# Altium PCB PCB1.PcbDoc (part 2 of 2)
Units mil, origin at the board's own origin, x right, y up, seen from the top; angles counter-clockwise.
Board outline 1707.5 x 1259.84 mil, 4 copper layers (Top Layer, GND, Sign, Bottom Layer), stack 23.756 mil thick; 63 components, 56 nets, 288 pads, 252 vias.
Unrouted connection lines stored in the file: 1.
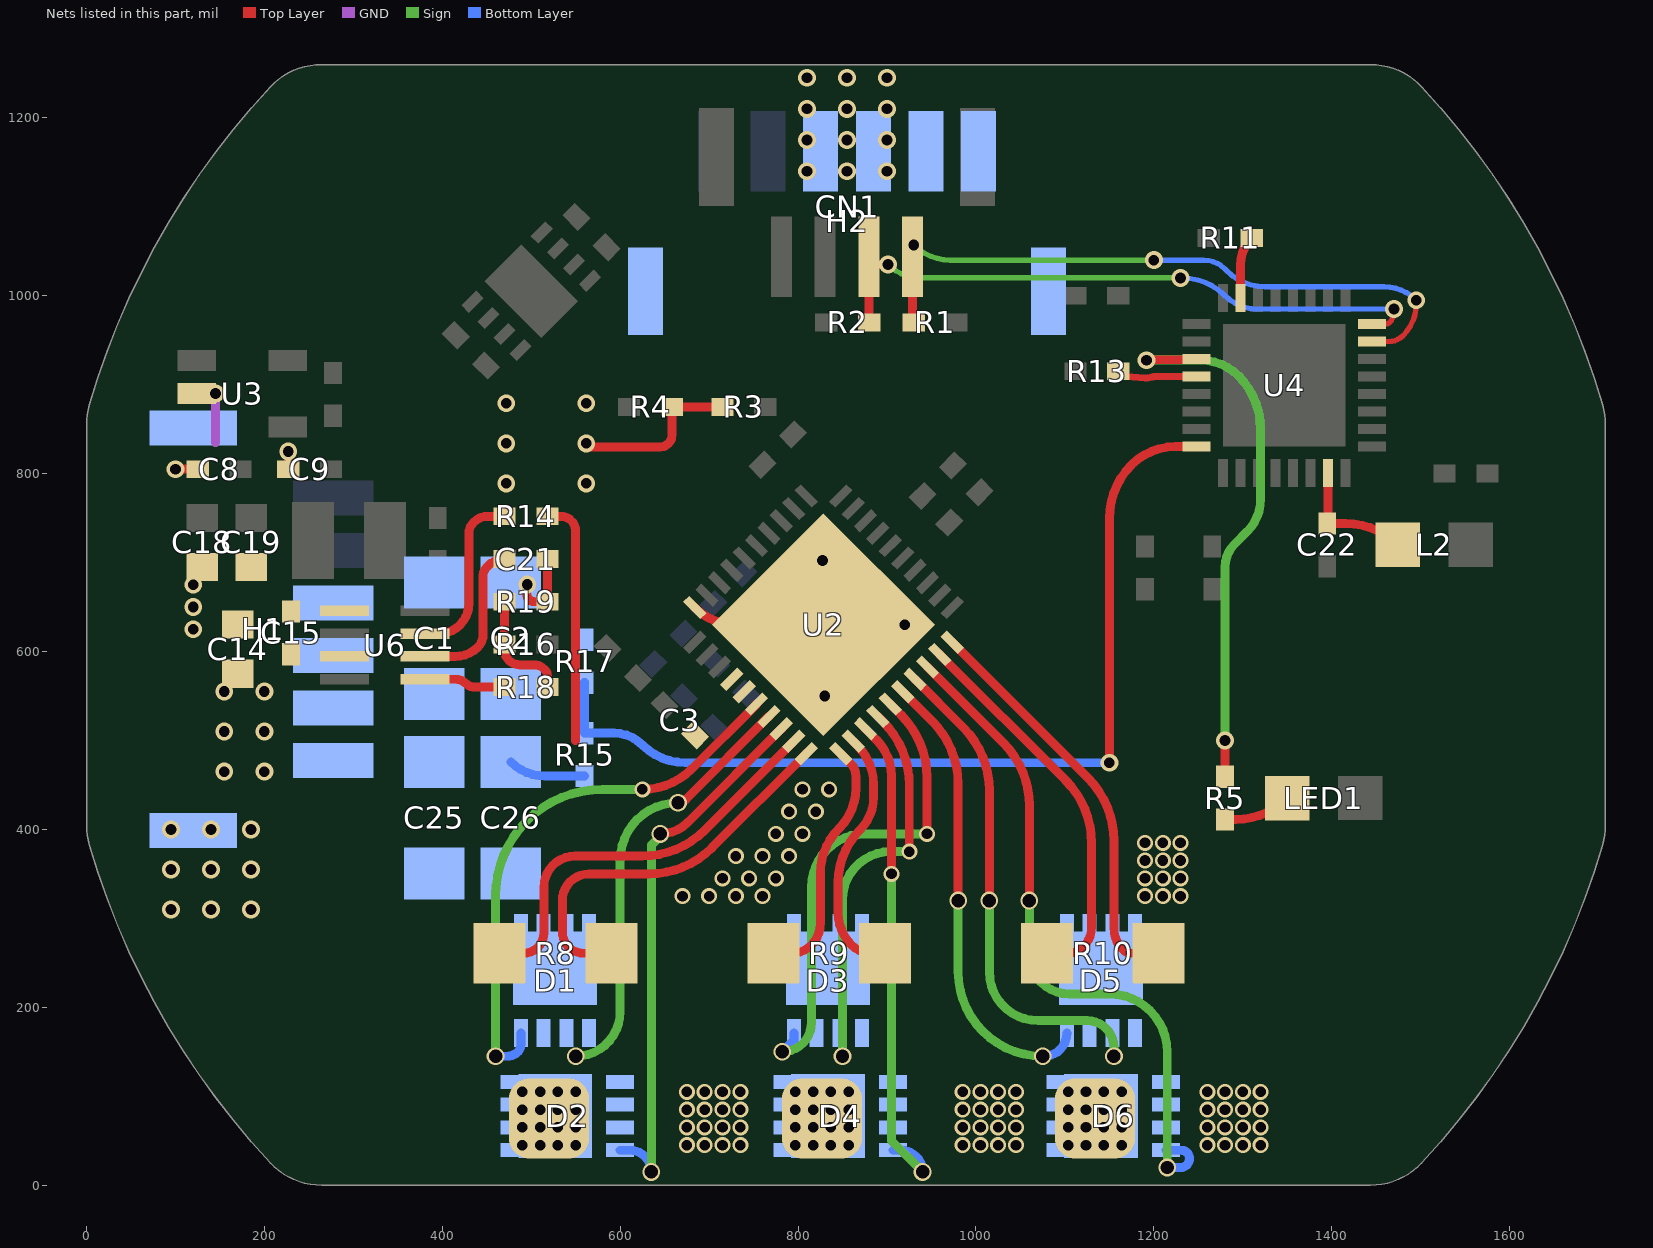
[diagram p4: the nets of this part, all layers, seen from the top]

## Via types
v1: diameter 18, hole 12, Top Layer to Bottom Layer, tented both sides, 138 vias
v2: diameter 20, hole 12, Top Layer to Bottom Layer, tented both sides, 100 vias
v3: diameter 20, hole 15, Top Layer to Bottom Layer, tented both sides, 14 vias

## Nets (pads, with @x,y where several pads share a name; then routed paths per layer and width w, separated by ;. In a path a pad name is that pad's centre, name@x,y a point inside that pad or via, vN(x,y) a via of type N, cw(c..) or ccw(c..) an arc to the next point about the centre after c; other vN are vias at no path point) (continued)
NetC21_2: C21.2 U6.2 | length 177.5
  Top Layer w10: U6.2@380.55,594.41 414.43,594.41 ccw(c414.43,630.57) 440,605 ccw(c425.51,619.49) 446,619.49 446,685.88 cw(c456,685.84) 446.87,689.91 cw(c466.24,681.2) 451.22,696.22 cw(c470,677.44) C21.2@470,704
NetC22_2: C22.2 L2.2 U4.15 | length 142.4
  Top Layer w10: U4.15@1395.78,800.79 1395.78,745.88 cw(c1393.12,745.88) C22.2@1395,744 1415.48,744 cw(c1415.48,661.38) L2.2@1473.9,719.8
NetD1_G: D1.G U2.6 | length 898.7
  Top Layer w10: U2.6@753.34,540.92 680.34,467.92 ; 680.34,467.92 cw(c625,523.27) v1(625,445) ccw(c625,523.27) 680.34,467.92
  Sign w10: v3(460,145) 460,325 ; 580,445 v1(625,445) ; 460,325 cw(c580,325) 580,445 ccw(c580,325) 460,325
  Bottom Layer w10: v3(460,145) 472.93,145 ; D1.G@488.34,170.94 D1.G@488.34,158.07 ; 472.93,145 ccw(c472.93,162.07) 485,150 cw(c472.93,162.07) 472.93,145 ; D1.G@488.34,158.07 cw(c476.93,158.07) 485,150 ccw(c476.93,158.07) D1.G@488.34,158.07
NetD2_G: D2.G U2.8 | length 650.9
  Top Layer w10: U2.8@781.18,513.08 675.89,407.8 ; 675.89,407.8 cw(c645,438.69) v3(645,395) ccw(c645,438.69) 675.89,407.8
  Sign w10: v3(635,15) 635,382.29 645,392.29 v3(645,395)
  Bottom Layer w10: D2.G@599.61,39.33 610.67,39.33 cw(c610.67,15) v3(635,15)
NetD2_S: D2.S R8.2 U2.9 | length 633.5
  Top Layer w10: R8.2@464.6,260.79 R8.2@491.3,260.79 ; U2.9@795.1,499.16 695.23,399.29 ; R8.2@491.31,260.79 ccw(c491.31,283.69) 514.21,283.69 ; R8.2@491.31,260.79 ccw(c491.31,283.69) 514.21,283.69 ; 514.21,283.69 514.21,335.07 ; 514.21,335.07 cw(c549.14,335.07) 549.14,370 ; 514.21,335.07 cw(c549.14,335.07) 549.14,370 ; 549.14,370 624.52,370 ; 624.52,370 ccw(c624.52,470) 695.23,399.29 ; 624.52,370 ccw(c624.52,470) 695.23,399.29
  other v1: 675,45 695,45 715,45 735,45 675,65 695,65 715,65 735,65 675,85 695,85 715,85 735,85 675,105 695,105 715,105 735,105
NetD3_G: D3.G U2.15 | length 631.6
  Top Layer w10: U2.15@903.67,540.92 915.71,528.88 ; v1(945,395) 945,458.17 ; 915.71,528.88 cw(c845,458.17) 945,458.17 ccw(c845,458.17) 915.71,528.88
  Sign w10: v3(782.17,150) ccw(c782.17,182.83) 815,182.83 815,335 cw(c875,335) 875,395 v1(945,395)
  Bottom Layer w10: v3(782.17,150) 795.24,163.07 D3.G@795.24,170.94
NetD4_G: D4.G U2.13 | length 614.9
  Top Layer w10: U2.13@875.83,513.08 888.09,500.82 ; v1(905,350) 905,460 ; 888.09,500.82 cw(c847.28,460) 905,460 ccw(c847.28,460) 888.09,500.82
  Sign w10: v1(905,350) 905,50 v3(940,15)
  Bottom Layer w10: D4.G@906.5,39.33 915.67,39.33 cw(c915.67,15) v3(940,15)
NetD4_S: D4.S R9.2 U2.12 | length 405
  Top Layer w10: 845,339.64 cw(c930.36,339.64) 870,400 ; 845,306.21 845,339.64 ; U2.12@861.91,499.16 U2.12@866.57,494.49 ; 870,400 ccw(c833.79,436.21) 885,436.21 ; 885,436.21 885,450 ; R9.2@897.5,260.79 R9.2@882.23,260.79 ; 860,270 ccw(c882.23,292.23) R9.2@882.23,260.79 ; 860,270 cw(c896.21,306.21) 845,306.21 ccw(c896.21,306.21) 860,270 ; 860,270 ccw(c882.23,292.23) R9.2@882.23,260.79 ; U2.12@866.57,494.49 cw(c822.08,450) 885,450 ccw(c822.08,450) U2.12@866.57,494.49
  other v1: 985,45 1005,45 1025,45 1045,45 985,65 1005,65 1025,65 1045,65 985,85 1005,85 1025,85 1045,85 985,105 1005,105 1025,105 1045,105
NetD5_G: D5.G U2.16 | length 606.1
  Top Layer w10: U2.16@917.59,554.83 950.71,521.71 ; v3(980,320) 980,451 ; 950.71,521.71 cw(c880,451) 980,451 ccw(c880,451) 950.71,521.71
  Sign w10: 980,240 ccw(c1075,240) v3(1075,145) ; 980,240 v3(980,320)
  Bottom Layer w10: v3(1075,145) 1076.19,145 ccw(c1076.18,170.94) D5.G@1102.12,170.94
NetD6_G: D6.G U2.18 | length 1043.1
  Top Layer w10: U2.18@945.43,582.67 1030.71,497.39 ; v3(1060,320) 1060,426.68 ; 1030.71,497.39 cw(c960,426.68) 1060,426.68 ccw(c960,426.68) 1030.71,497.39
  Sign w10: 1060,259.87 v3(1060,320) ; 1150,215 1104.87,215 ; v3(1215,20) 1215,150 ; 1104.87,215 cw(c1104.87,259.87) 1060,259.87 ccw(c1104.87,259.87) 1104.87,215 ; 1150,215 cw(c1150,150) 1215,150 ccw(c1150,150) 1150,215
  Bottom Layer w10: D6.G@1213.39,39.33 1230.67,39.33 cw(c1230.67,30) 1240,30 ; v3(1215,20) 1230,20 ; 1240,30 cw(c1230,30) 1230,20 ccw(c1230,30) 1240,30
NetD6_S: D6.S R10.2 U2.19 | length 562.3
  Top Layer w10: U2.19@959.35,596.59 1100.71,455.23 ; R10.2@1079.6,260.79 R10.2@1103.83,260.81 ; 1130,290 1130,384.52 ; 1100.71,455.23 cw(c1030,384.52) 1130,384.52 ccw(c1030,384.52) 1100.71,455.23 ; R10.2@1103.83,260.81 ccw(c1102.77,286.62) 1121.04,268.36 ; R10.2@1103.84,260.81 ccw(c1102.77,286.62) 1121.04,268.36 ; 1121.04,268.36 ccw(c1099.39,290) 1130,290 cw(c1099.39,290) 1121.04,268.36
  other v1: 1260,45 1280,45 1300,45 1320,45 1260,65 1280,65 1300,65 1320,65 1260,85 1280,85 1300,85 1320,85 1260,105 1280,105 1300,105 1320,105
NetLED1_1: LED1.1 R5.2 | length 76.2
  Top Layer w10: R5.2@1280,411.12 1291.81,411.12 ccw(c1291.81,493.07) LED1.1@1349.75,435.12
NetR11_2: R11.2 U4.31 | length 70.7
  Top Layer w10: U4.31@1297.36,997.64 1297.36,1034.48 cw(c1340.52,1034.48) R11.2@1310,1065
NetR13_2: R13.2 U4.4 | length 90.3
  Top Layer w8: R13.2@1160,915 1168.5,909 1190.29,907.57 ccw(c1191.65,927.53) 1198.19,908.63 cw(c1200.79,901.06) 1200.79,909.06 U4.4@1248.15,909.06
NetR14_2: R14.2 U6.3 | length 198.1
  Top Layer w10: U6.3@380.55,620 395.86,620 ccw(c395.86,654.14) 420,630 ccw(c395.86,654.14) 430,654.14 430,732.88 ; 430,732.93 cw(c447.07,732.93) 435,745 435.86,745.86 cw(c450.69,731.03) 450.69,752 R14.2@470,752
NetR15_1: R15.1 R17.1 U4.8 | length 1075.9
  Top Layer w10: v2(1150,475) 1150,749.64 cw(c1235.36,749.64) 1175,810 cw(c1224.06,760.94) 1224.06,830.32 U4.8@1248.15,830.32
  Bottom Layer w10: R17.1@560,565 R15.1@560,508.2 592.97,508.2 593.03,508.2 cw(c593.13,463.13) 625,495 ; 625,495 ccw(c673.28,543.28) 673.32,475 ; 673.36,475 v2(1150,475)
NetR16_1: R16.1 R18.2 R19.2 | length 130.9
  Top Layer w10: R19.2@470,656 R16.1@470,608 470,602.07 ccw(c487.07,602.07) 475,590 ccw(c487.07,602.07) 487.07,585 502.93,585 cw(c502.93,567.93) 515,580 ; 515,580 cw(c507.27,572.27) 518.2,572.27 R18.2@518.2,560
NetR18_1: R18.1 U6.1 | length 91.8
  Top Layer w10: U6.1@380.55,568.82 415.78,568.82 cw(c415.78,555.78) 425,565 ; 425,565 ccw(c437.07,577.07) 437.07,560 R18.1@470,560
PGND: C1.1 C2.1 C8.1 C9.1 C14.1 C15.1 C18.1 C19.1 C21.1 C25.1 C26.1 H1.3 H1.4 H1.7 H1.8 H2.3 H2.4 H2.7 H2.8 R3.2 R4.2 R8.1 R9.1 R10.1 R17.2 R19.1 U2.10 U2.11 U2.20 U2.40 U2.41 U3.2 U6.5 | length 2089.3
  Top Layer w10: v2(100,805) C8.1@125,805 ; U3.2@123.81,890 v2(145,890) ; C9.1@226.8,805 v2(226.8,824.79) ; v2(495.48,675.35) 495,675.35 495,665 ccw(c504,665) 504,656 R19.1@518.2,656 C21.1@518.2,704 ; 535,285 ccw(c559.21,285) 559.21,260.79 R8.1@590,260.79 ; 535,285 535,320 ; v2(561.82,834) ccw(c565.82,834) 565.82,830 645,830 ccw(c645,843.2) 658.2,843.2 R4.2@658.2,875 R3.2@715,875 ; 565,350 632.35,350 ; R9.1@772.1,260.79 792.77,260.79 ccw(c792.77,292.23) 815,270 ; U2.10@809.01,485.24 703.07,379.29 ; 825,350 cw(c897.43,350) 846.2,401.2 ; 825,294.14 825,350 ; U2.41@828.5,630 U2.41@730.8,630 ; U2.11@847.99,485.24 859.18,474.05 ; 865,446.57 865,460 ; U2.20@973.27,610.51 1125.71,458.06 ; 1155,289.14 ccw(c1189.14,289.14) 1165,265 ; 1155,289.14 1155,387.35 ; 1165,265 ccw(c1175.16,275.16) 1175.16,260.79 R10.1@1205,260.79 ; 632.35,350 ccw(c632.35,450) 703.06,379.29 ; 632.35,350 ccw(c632.35,450) 703.06,379.29 ; U2.41@730.79,630 cw(c730.79,696.54) U2.40@683.74,649.49 ccw(c730.79,696.54) 687.88,645.69 ccw(c730.79,696.54) U2.41@730.79,630 ; 846.2,401.2 ccw(c800.86,446.57) 865,446.57 cw(c800.86,446.57) 846.2,401.2 ; 859.18,474.05 cw(c845.12,460) 865,460 ccw(c845.12,460) 859.18,474.05 ; 1125.71,458.06 cw(c1055,387.35) 1155,387.35 ccw(c1055,387.35) 1125.71,458.06 ; 535,320 cw(c565,320) 565,350 ccw(c565,320) 535,320 ; 815,270 ccw(c790.86,294.14) 825,294.14 cw(c790.86,294.14) 815,270
  GND w10: 145,835 v2(145,890)
  other v1: 670,325 700,325 730,325 760,325 1190,325 1210,325 1230,325 715,345 745,345 775,345 1190,345 1210,345 1230,345 1190,365 1210,365 1230,365 730,370 760,370 790,370 1190,385 1210,385 1230,385 775,395 805,395 790,420 820,420 805,445 835,445
  other v2: 95,310 140,310 185,310 95,355 140,355 185,355 95,400 140,400 185,400 830,550 120,625 920,630 120,650 120,675 827.42,702.42 471.82,789 561.82,789 471.82,834 471.82,879 561.82,879 810,1140 855,1140 900,1140 810,1175 855,1175 900,1175 810,1210 855,1210 900,1210 810,1245 855,1245 900,1245
SHA: D1.S D2.D pad.2@520,75 U2.7 | length 492.5
  Top Layer w10: v3(665,430) ccw(c665,442.71) 673.99,433.72 U2.7@767.26,526.99
  Sign w10: v3(550,145) ccw(c550,195) 600,195 ; 600,365 cw(c665,365) v3(665,430) ; 600,195 600,365
  other v1: 490,45 510,45 530,45 550,45 490,65 510,65 530,65 550,65 490,85 510,85 530,85 550,85 490,105 510,105 530,105 550,105
SHB: D3.S D4.D pad.2@826.89,75 U2.14 | length 607.3
  Top Layer w10: U2.14@889.75,526.99 U2.14@895.71,521.03 ; v1(925,375) 925,450.32 ; U2.14@895.71,521.03 cw(c825,450.32) 925,450.32 ccw(c825,450.32) U2.14@895.71,521.03
  Sign w10: v3(850,145) 850,321.2 ; v1(925,375) 903.8,375 ; 903.8,375 ccw(c903.8,321.2) 850,321.2 cw(c903.8,321.2) 903.8,375
  other v1: 796.89,45 816.89,45 836.89,45 856.89,45 796.89,65 816.89,65 836.89,65 856.89,65 796.89,85 816.89,85 836.89,85 856.89,85 796.89,105 816.89,105 836.89,105 856.89,105
SHC: D5.S D6.D pad.2@1133.78,75 U2.17 | length 769.6
  Top Layer w10: U2.17@931.51,568.76 985.71,514.56 ; v3(1015,320) 1015,443.84 ; 985.71,514.55 cw(c915,443.84) 1015,443.84 ccw(c915,443.84) 985.71,514.55
  Sign w10: 1015,239.99 v3(1015,320) ; 1125,185 1069.99,185 ; v3(1155,145) 1155,155 ; 1069.99,185 cw(c1069.99,239.99) 1015,239.99 ccw(c1069.99,239.99) 1069.99,185 ; 1125,185 cw(c1125,155) 1155,155 ccw(c1125,155) 1125,185
  other v1: 1103.78,45 1123.78,45 1143.78,45 1163.78,45 1103.78,65 1123.78,65 1143.78,65 1163.78,65 1103.78,85 1123.78,85 1143.78,85 1163.78,85 1103.78,105 1123.78,105 1143.78,105 1163.78,105
STATE_LED: R5.1 U4.3 | length 634.7
  Top Layer w10: v2(1191.65,927.53) 1237.4,928.24 U4.3@1248.15,928.75 ; R5.1@1280,459.32 v2(1280,500)
  Sign w10: v2(1191.65,927.53) 1252.69,927.53 cw(c1252.69,867.69) 1295,910 ; v2(1280,500) 1280,695 cw(c1316.21,695) 1290.61,720.61 1305,735 ; 1295,910 cw(c1234.64,849.64) 1320,849.64 1320,771.21 cw(c1268.79,771.21) 1305.01,735.01
SWCLK: CN1.3 R2.1 U4.24 | length 736.1
  Top Layer w6: U4.24@1445,968.11 1460.44,968.11 ccw(c1460.44,974.56) 1465,970 ccw(c1452.93,982.07) 1470,982.07 v2(1470,985)
  Top Layer w10: CN1.3@879.61,1060.39 CN1.3@879.61,1043.9 ; R2.1@880,970 879.8,970.19 CN1.3@879.8,1041.62 ; v2(901.01,1035) 886.42,1035 CN1.3@879.8,1041.62 ; CN1.3@879.61,1043.9 879.61,1041.81 CN1.3@879.8,1041.62 ; CN1.3@879.61,1043.9 879.8,1043.71 CN1.3@879.8,1041.62
  Sign w6: v2(901.01,1035) ccw(c937.22,1071.21) 903.9,1032.32 ccw(c937.22,1071.21) 937.22,1020 v2(1230,1020)
  Bottom Layer w6: v2(1230,1020) 1231.72,1020 cw(c1231.72,951.72) 1280,1000 ccw(c1316.21,1036.21) 1316.21,985 v2(1470,985)
SWDIO: CN1.4 R1.1 U4.23 | length 772
  Top Layer w6: U4.23@1445,948.43 1464.14,948.43 ccw(c1464.14,970.86) 1480,955 ; 1480,955 ccw(c1443.79,991.21) 1495,991.21 v2(1495,995)
  Top Layer w10: CN1.4@928.82,1077.37 CN1.4@928.82,1058.25 ; v2(930,1057.07) CN1.4@928.82,1058.25 ; R1.1@930,970 cw(c932.85,972.85) 928.82,972.85 CN1.4@928.82,1043.9 CN1.4@928.82,1058.25
  Sign w6: v2(930,1057.07) ccw(c971.21,1098.28) 971.21,1040 v2(1200,1040)
  Bottom Layer w6: v2(1200,1040) 1255.86,1040 cw(c1255.86,1005.86) 1280,1030 ; 1280,1030 1282.32,1027.68 ccw(c1325,1070.36) 1325,1010 1458.79,1010 cw(c1458.79,958.79) v2@1495,995
VBUS: C1.2 C2.2 C3.2 C14.2 C15.2 C25.2 C26.2 D1.D D3.D D5.D H1.1 H1.2 H2.1 H2.2 R14.1 R15.2 U2.4 U2.5 U6.7 | length 363.8
  Top Layer w10: R14.1@518.2,752 533,752 cw(c533,735) 550,735 550,500
  Bottom Layer w10: C26.2@477,476 ccw(c515.63,514.63) 515.63,460 R15.2@560,460
  other v2: 155,465 200,465 155,510 200,510 155,555 200,555
pads on no net: CN1.5 CN1.6 U2.28 U3.4 U4.29 U4.30 U5.1 U5.2 U5.3 U5.6 U5.9 U5.10 U5.11 U5.15 U5.16 U5.17 U6.8

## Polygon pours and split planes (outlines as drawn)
PGND on Bottom Layer "PGND_L04_P057" (solid, remove dead copper, pour order 57): 206.79,24.97 cw(c853.88,629.92) 3.25,382.67 cw(c78.86,404.65) 0.12,404.65 0.13,855.2 cw(c78.87,855.2) 3.25,877.17 cw(c853.88,629.92) 206.79,1234.88 cw(c264.31,1181.1) 264.31,1259.84 1443.44,1259.84 cw(c1443.44,1181.1) 1500.96,1234.88 cw(c853.88,629.92) 1704.5,877.17 cw(c1628.89,855.2) 1707.62,855.2 1707.62,404.65 cw(c1628.89,404.65) 1704.5,382.67 cw(c853.88,629.92) 1500.96,24.97 cw(c1443.44,78.74) 1443.44,0 264.31,0 cw(c264.31,78.74)
PGND on Bottom Layer "NONET_L-01_P-001" (solid, pour order 49): 230,685 ccw(c230,680) 225,680 225,580 ccw(c235,580) 235,570 320,570 ccw(c320,580) 330,580 330,605 cw(c340,605) 340,615 525,615 cw(c525,605) 535,605 535,600 ccw(c545,600) 545,590 580,590 ccw(c580,595) 585,595 585,650 cw(c595,650) 595,660 625,660 ccw(c625,670) 635,670 635,925 cw(c655,925) 655,945 890,945 ccw(c890,965) 910,965 910,1225 ccw(c895,1225) 895,1240 810,1240 ccw(c810,1230) 800,1230 800,1115 cw(c785,1115) 785,1100 775,1100 ccw(c775,1090) 765,1090 765,1075 cw(c750,1075) 750,1060 618.28,1060 ccw(c618.28,991.72) 570,1040 434.29,904.29 ccw(c505,833.58) 405,833.58 405,730 cw(c390,730) 390,715 355,715 ccw(c355,705) 345,705 345,700 cw(c330,700) 330,685
VBUS on Bottom Layer "Bottom Layer-VBUS" (solid, pour order 48): 1150,205 1533.58,205 ccw(c1533.58,305) 1604.29,234.29 1620,250 1675,355 ccw(c1626.72,403.28) 1695,403.28 1695,860 1660,965 1570,1130 1485,1215 ccw(c1424.64,1154.64) 1424.64,1240 949.14,1240 ccw(c949.14,1205.86) 925,1230 ccw(c949.14,1205.86) 915,1205.86 915,1101.21 ccw(c966.21,1101.21) 930,1065 ccw(c942.07,1077.07) 942.07,1060 1413.79,1060 cw(c1413.79,1008.79) 1450,1045 1454.39,1040.61 ccw(c1480,1066.21) 1480,1030 1483.79,1030 cw(c1483.79,978.79) 1520,1015 cw(c1471.72,966.72) 1540,966.72 1540,835.36 cw(c1454.65,835.35) 1515,775 ccw(c1575.36,714.64) 1490,714.64 1490,373.28 cw(c1421.72,373.28) 1470,325 cw(c1421.72,373.28) 1421.72,305 365,305 cw(c365,330) 340,330 340,410 515,410 ccw(c515,425) 530,425 530,585 ccw(c510,585) 510,605 355,605 ccw(c355,590) 340,590 340,585 cw(c320,585) 320,565 230,565 cw(c230,575) 220,575 220,605 ccw(c210,605) 210,615 145,615 ccw(c145,605) 135,605 135,435 ccw(c145,435) 145,425 205,425 cw(c205,415) 215,415 215,270 ccw(c280,270) 280,205 1150,205
3V3 on Bottom Layer "NONET_L-01_P-001" (solid, pour order 42): 783.54,671.46 ccw(c775,662.93) 775,675 772.07,675 ccw(c772.07,657.93) 760,670 748.54,658.54 cw(c740,667.07) 740,655 737.07,655 cw(c737.07,672.07) 725,660 713.54,671.46 ccw(c705,662.93) 705,675 ccw(c705,662.93) 696.46,671.46 657.07,632.07 ccw(c674.14,615) 650,615 ccw(c662.07,615) 653.54,606.46 662.93,597.07 cw(c645.86,580) 670,580 cw(c657.93,580) 666.46,571.46 653.54,558.54 ccw(c662.07,550) 650,550 ccw(c662.07,550) 653.54,541.46 666.46,528.54 ccw(c675,537.07) 675,525 ccw(c675,537.07) 683.54,528.54 731.46,576.46 ccw(c722.93,585) 735,585 cw(c759.14,585) 742.07,602.07 791.46,651.46 ccw(c782.93,660) 795,660 790,665
NetD6_S on Bottom Layer "NONET_L-01_P-001" (solid, pour order 38): 1203.78,125 ccw(c1203.78,120) 1198.78,120 1198.78,30 ccw(c1203.78,30) 1203.78,25 1368.78,25 ccw(c1368.78,30) 1373.78,30 1373.78,120 ccw(c1368.78,120) 1368.78,125
NetD4_S on Bottom Layer "NONET_L-01_P-001" (solid, pour order 37): 896.89,125 ccw(c896.89,120) 891.89,120 891.89,30 ccw(c896.89,30) 896.89,25 1061.89,25 ccw(c1061.89,30) 1066.89,30 1066.89,120 ccw(c1061.89,120) 1061.89,125
NetD2_S on Bottom Layer "NONET_L-01_P-001" (solid, pour order 36): 590,125 ccw(c590,120) 585,120 585,30 ccw(c590,30) 590,25 755,25 ccw(c755,30) 760,30 760,120 ccw(c755,120) 755,125
SHC on Bottom Layer "NONET_L-01_P-001" (solid, pour order 35): 1118.78,195 ccw(c1118.78,190) 1113.78,190 1113.78,135 cw(c1108.78,135) 1108.78,130 1078.78,130 ccw(c1078.78,125) 1073.78,125 1073.78,30 ccw(c1078.78,30) 1078.78,25 1183.78,25 ccw(c1183.78,30) 1188.78,30 1188.78,125 cw(c1193.78,125) 1193.78,130 1233.78,130 ccw(c1233.78,135) 1238.78,135 1238.78,190 ccw(c1233.78,190) 1233.78,195
SHB on Bottom Layer "NONET_L-01_P-001" (solid, pour order 34): 811.89,195 ccw(c811.89,190) 806.89,190 806.89,135 cw(c801.89,135) 801.89,130 771.89,130 ccw(c771.89,125) 766.89,125 766.89,30 ccw(c771.89,30) 771.89,25 876.89,25 ccw(c876.89,30) 881.89,30 881.89,125 cw(c886.89,125) 886.89,130 926.89,130 ccw(c926.89,135) 931.89,135 931.89,190 ccw(c926.89,190) 926.89,195
SHA on Bottom Layer "NONET_L-01_P-001" (solid, pour order 33): 505,195 ccw(c505,190) 500,190 500,135 cw(c495,135) 495,130 465,130 ccw(c465,125) 460,125 460,30 ccw(c465,30) 465,25 570,25 ccw(c570,30) 575,30 575,125 cw(c580,125) 580,130 620,130 ccw(c620,135) 625,135 625,190 ccw(c620,190) 620,195
DGND on Top Layer "DGND_L01_P059" (solid, remove dead copper, pour order 59): 206.79,24.97 cw(c853.88,629.92) 3.25,382.67 cw(c78.86,404.65) 0.12,404.65 0.13,855.2 cw(c78.87,855.2) 3.25,877.17 cw(c853.88,629.92) 206.79,1234.88 cw(c264.31,1181.1) 264.31,1259.84 1443.44,1259.84 cw(c1443.44,1181.1) 1500.96,1234.88 cw(c853.88,629.92) 1704.5,877.17 cw(c1628.89,855.2) 1707.62,855.2 1707.62,404.65 cw(c1628.89,404.65) 1704.5,382.67 cw(c853.88,629.92) 1500.96,24.97 cw(c1443.44,78.74) 1443.44,0 264.31,0 cw(c264.31,78.74)
PGND on Top Layer "NONET_L-01_P-001" (solid, pour order 39): 1165,285 1165,230 ccw(c1170,230) 1170,225 1245,225 ccw(c1245,230) 1250,230 1250,395 ccw(c1245,395) 1245,400 1172.72,400 ccw(c1172.72,393.16) 1165.89,393.16
PGND on Top Layer "NONET_L-01_P-001" (solid, pour order 61): 565,335 ccw(c565,325) 555,325 555,235 ccw(c565,235) 565,225 800,225 ccw(c800,230) 805,230 805,346.72 cw(c873.28,346.72) 825,395 828.79,398.79 ccw(c777.57,450) 850,450 850,457.93 ccw(c832.93,457.93) 845,470 ccw(c832.93,457.93) 832.93,475 825,475 ccw(c825,462.93) 816.46,471.46 709.29,364.29 cw(c638.58,435) 638.58,335 635,335
PGND on Top Layer "NONET_L-01_P-001" (solid, pour order 55): 205,715 cw(c205,705) 215,705 215,675 ccw(c225,675) 225,665 315,665 cw(c315,660) 320,660 320,640 cw(c315,640) 315,635 255,635 ccw(c255,630) 250,630 cw(c245,630) 245,625 205,625 ccw(c205,620) 200,620 cw(c190,620) 190,610 110,610 cw(c110,615) 105,615 105,710 cw(c110,710) 110,715
3V3 on Top Layer "NONET_L-01_P-001" (solid, pour order 54): 165,945 165,870 250,870 cw(c250,865) 255,865 255,795 ccw(c260,795) 260,790 295,790 ccw(c295,795) 300,795 300,890 ccw(c295,890) 295,895 265,895 cw(c265,900) 260,900 260,940 ccw(c255,940) 255,945
5V on Top Layer "NONET_L-01_P-001" (solid, pour order 50): 190,765 190,812.93 ccw(c172.93,812.93) 185,825 ccw(c172.93,812.93) 172.93,830 167.07,830 cw(c167.07,847.07) 155,835 153.54,836.46 cw(c162.07,845) 150,845 150,857.93 ccw(c132.93,857.93) 145,870 ccw(c132.93,857.93) 132.93,875 107.07,875 cw(c107.07,892.07) 95,880 cw(c107.07,892.07) 90,892.07 90,900 cw(c102.07,900) 93.54,908.54 95,910 cw(c107.07,897.93) 107.07,915 137.93,915 ccw(c137.93,932.07) 150,920 151.46,921.46 ccw(c142.93,930) 155,930 155,937.93 ccw(c137.93,937.93) 150,950 148.54,951.46 ccw(c140,942.93) 140,955 67.07,955 ccw(c67.07,937.93) 55,950 ccw(c67.07,937.93) 50,937.93 50,847.07 ccw(c67.07,847.07) 55,835 ccw(c67.07,847.07) 67.07,830 122.93,830 cw(c122.93,812.93) 135,825 137.93,822.07 cw(c120.86,805) 145,805 145,765
VBUS on Top Layer "NONET_L-01_P-001" (solid, pour order 47): 335,600 ccw(c330,600) 330,605 255,605 cw(c255,610) 250,610 ccw(c245,610) 245,615 210,615 ccw(c210,610) 205,610 cw(c200,610) 200,605 145,605 ccw(c145,595) 135,595 135,430 ccw(c155,430) 155,410 335,410 335,535 ccw(c320,535) 320,550 265,550 cw(c265,560) 255,560 255,570 cw(c265,570) 265,580 330,580 ccw(c330,585) 335,585
5V on Top Layer "NONET_L-01_P-001" (solid, pour order 46): 120,775 ccw(c120,765) 110,765 110,735 ccw(c120,735) 120,725 215,725 cw(c215,715) 225,715 225,685 ccw(c235,685) 235,675 275,675 ccw(c275,685) 285,685 285,765 ccw(c275,765) 275,775
NetC10_2 on Top Layer "NONET_L-01_P-001" (solid, pour order 45): 265,630 ccw(c265,625) 260,625 260,615 ccw(c265,615) 265,610 340,610 ccw(c340,620) 350,620 350,670 cw(c355,670) 355,675 ccw(c355,680) 360,680 360,765 ccw(c355,765) 355,770 315,770 ccw(c315,765) 310,765 310,680 ccw(c315,680) 315,675 320,675 cw(c320,670) 325,670 325,635 cw(c320,635) 320,630
VBUS on Top Layer "NONET_L-01_P-001" (solid, pour order 44): 757.5,562.5 738.54,581.46 ccw(c732.51,578.97) 735,585 ccw(c726.48,581.48) 730,590 660.61,520.61 cw(c635,546.2) 635,510 230,510 ccw(c229.99,485.88) 212.93,502.93 210,500 210,427.07 ccw(c227.07,427.07) 215,415 ccw(c227.07,427.07) 227.07,410 570.86,410 ccw(c570.86,444.14) 595,420 ccw(c582.93,432.07) 600,432.07 600,442.93 cw(c617.07,442.93) 605,455 cw(c617.07,442.93) 617.07,460 647.93,460 ccw(c647.93,477.07) 660,465
NetD2_S on Top Layer "NONET_L-01_P-001" (solid, pour order 40): 435,295 ccw(c435,290) 430,290 430,175 ccw(c445,175) 445,160 550,160 cw(c550,135) 575,135 575,40 ccw(c595,40) 595,20 740,20 ccw(c740,40) 760,40 760,200 ccw(c740,200) 740,220 500,220 cw(c500,225) 495,225 495,290 ccw(c490,290) 490,295
NetD6_S on Top Layer "Top Layer-NetD6_S" (solid, pour order 43): 1065,220 cw(c1065,215) 1070,215 1070,160 ccw(c1075,160) 1075,155 1195,155 cw(c1195,115) 1235,115 1235,40 ccw(c1250,40) 1250,25 1325,25 ccw(c1325,40) 1340,40 1340,205 ccw(c1325,205) 1325,220 1125,220 cw(c1125,230) 1115,230 1115,295 ccw(c1110,295) 1110,300 1050,300 ccw(c1050,295) 1045,295 1045,225 ccw(c1050,225) 1050,220
NetD4_S on Top Layer "NONET_L-01_P-001" (solid, pour order 41): 870,300 ccw(c870,295) 865,295 865,165 ccw(c880,165) 880,150 890,150 cw(c890,125) 915,125 915,40 ccw(c930,40) 930,25 1050,25 ccw(c1050,40) 1065,40 1065,200 ccw(c1050,200) 1050,215 950,215 cw(c950,220) 945,220 945,295 ccw(c940,295) 940,300
3V3 on Sign "3V3_L03_P051" (solid, remove dead copper, pour order 51): 206.79,24.97 cw(c853.88,629.92) 3.25,382.67 cw(c78.86,404.65) 0.12,404.65 0.13,855.2 cw(c78.87,855.2) 3.25,877.17 cw(c853.88,629.92) 206.79,1234.88 cw(c264.31,1181.1) 264.31,1259.84 1443.44,1259.84 cw(c1443.44,1181.1) 1500.96,1234.88 cw(c853.88,629.92) 1704.5,877.17 cw(c1628.89,855.2) 1707.62,855.2 1707.62,404.65 cw(c1628.89,404.65) 1704.5,382.67 cw(c853.88,629.92) 1500.96,24.97 cw(c1443.44,78.74) 1443.44,0 264.31,0 cw(c264.31,78.74)
DGND on GND "DGND_L02_P053" (solid, pour order 53): 0.27,860 1250,860 cw(c1250,855) 1255,855 1255,350 1694.31,350 ccw(c1372.67,443.5) 1707.62,443.51 1707.62,855.2 ccw(c1628.9,855.2) 1704.5,877.17 ccw(c853.88,629.92) 1500.96,1234.88 ccw(c1443.44,1181.1) 1443.44,1259.84 264.31,1259.84 ccw(c264.31,1181.1) 206.79,1234.88 ccw(c853.87,629.92) 3.25,877.17 ccw(c78.86,855.2)
PGND on GND "PGND_L02_P052" (solid, remove dead copper, pour order 52): 0.12,404.65 0.13,850 1245,850 1245,345 ccw(c1250,345) 1250,340 1690.91,340 cw(c853.88,629.92) 1500.96,24.97 cw(c1443.44,78.74) 1443.44,0 264.31,0 cw(c264.31,78.74) 206.79,24.97 cw(c853.88,629.92) 3.25,382.67 cw(c78.86,404.65)

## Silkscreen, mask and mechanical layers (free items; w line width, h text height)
Top Overlay:
  text "3V3 GND CLK DIO" at 695,910.29 h60
  text "L H G G V V" at 10.58,824.94 h120 r270
  text "A" at 500,140 h60
  text "B" at 806.89,140 h60
  text "C" at 1113.78,140 h60
Bottom Overlay:
  drawing of 3 lines, arcs and shapes, not listed
  text "V V G G H L" at 1049.94,855.58 h120
  text "ZQ FOC Lite" at 1679.93,752.32 h150
  text "2025/05/19" at 1680,545.41 h150
  text "DreamChaser Tech™" at 1679.93,360.72 h150
Mechanical 1:
  circle w0.5: c317.98,94.02 r49.21
  circle w0.5: c317.98,1165.82 r49.21
  circle w0.5: c1389.77,94.02 r49.21
  circle w0.5: c1389.77,1165.82 r49.21
  lines w2: -0.12,404.65 0.12,404.65
  lines w10: 0.12,404.65 ccw(c78.87,404.65) 3.25,382.67 ccw(c853.88,629.92) 206.79,24.97 ccw(c264.31,78.74) 264.31,0 1443.44,0 ccw(c1443.44,78.74) 1500.96,24.97 ccw(c853.88,629.92) 1704.5,382.67 ccw(c1628.88,404.65) 1707.62,404.65 1707.62,855.2 ccw(c1628.88,855.2) 1704.5,877.17 ccw(c853.88,629.92) 1500.96,1234.88 ccw(c1443.44,1181.1) 1443.44,1259.84 264.31,1259.84 ccw(c264.31,1181.1) 206.79,1234.88 ccw(c853.88,629.92) 3.25,877.17 ccw(c78.87,855.2) 0.12,855.2 0.12,404.65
